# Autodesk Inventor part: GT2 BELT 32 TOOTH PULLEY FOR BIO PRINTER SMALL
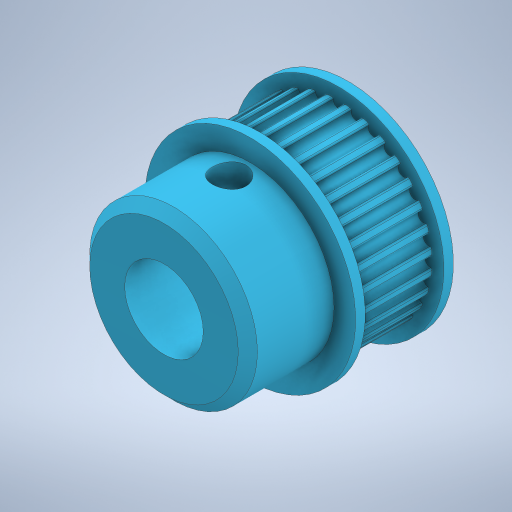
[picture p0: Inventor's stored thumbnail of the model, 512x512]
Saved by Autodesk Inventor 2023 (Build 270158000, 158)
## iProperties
Created: 2025-07
Part Number: GT2 BELT 32 TOOTH PULLEY FOR BIO PRINTER SMALL
Material: Generic
Document SubType Name: Modeling
Designer: erjon
Density: 1 g/cm^3
Appearance: Default
Author: erjon
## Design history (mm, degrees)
feature "Base1"
sketch "Sketch1"
  geometry: 1 further point
sketch "Sketch2"
  geometry: C1 r 10 at (0, 0) reference; C2 r 10 at (0, 0); 1 further point
  constraints: 1 centre point, 1 coincident
extrude "Extrusion1" cut sketch "Sketch2" distance "d0" = 6.2; taper "d1" = 0 deg
sketch "Sketch3" dims "d2" = 19.57
  geometry: L1 (0, 9.785)-(0, 9.035); L2 (0, 9.035)-(0, 9.585); C1 r 4 at (0, 0); A1 r 0.55 centre (0, 9.585) between (-0.517, 9.771) and (0.517, 9.771); A2 r 0.55 centre (-1.87, 9.401) between (-2.414, 9.483) and (-1.399, 9.685); A3 r 0.55 centre (-3.668, 8.855) between (-4.217, 8.829) and (-3.261, 9.226); A4 r 0.55 centre (-5.325, 7.97) between (-5.859, 7.837) and (-4.998, 8.412); A5 r 0.55 centre (-6.778, 6.778) between (-7.275, 6.543) and (-6.543, 7.275); A6 r 0.55 centre (-7.97, 5.325) between (-8.412, 4.998) and (-7.837, 5.859); A7 r 0.55 centre (-8.855, 3.668) between (-9.226, 3.261) and (-8.829, 4.217); A8 r 0.55 centre (-9.401, 1.87) between (-9.685, 1.399) and (-9.483, 2.414); A9 r 0.55 centre (-9.585, 0) between (-9.771, -0.517) and (-9.771, 0.517); A10 r 0.55 centre (-9.401, -1.87) between (-9.483, -2.414) and (-9.685, -1.399); A11 r 0.55 centre (-8.855, -3.668) between (-8.829, -4.217) and (-9.226, -3.261); A12 r 0.55 centre (-7.97, -5.325) between (-7.837, -5.859) and (-8.412, -4.998); A13 r 0.55 centre (-6.778, -6.778) between (-6.543, -7.275) and (-7.275, -6.543); A14 r 0.55 centre (-5.325, -7.97) between (-4.998, -8.412) and (-5.859, -7.837); A15 r 0.55 centre (-3.668, -8.855) between (-3.261, -9.226) and (-4.217, -8.829); A16 r 0.55 centre (-1.87, -9.401) between (-1.399, -9.685) and (-2.414, -9.483); A17 r 0.55 centre (0, -9.585) between (0.517, -9.771) and (-0.517, -9.771); A18 r 0.55 centre (1.87, -9.401) between (2.414, -9.483) and (1.399, -9.685); A19 r 0.55 centre (3.668, -8.855) between (4.217, -8.829) and (3.261, -9.226); A20 r 0.55 centre (5.325, -7.97) between (5.859, -7.837) and (4.998, -8.412); A21 r 0.55 centre (6.778, -6.778) between (7.275, -6.543) and (6.543, -7.275); A22 r 0.55 centre (7.97, -5.325) between (8.412, -4.998) and (7.837, -5.859); A23 r 0.55 centre (8.855, -3.668) between (9.226, -3.261) and (8.829, -4.217); A24 r 0.55 centre (9.401, -1.87) between (9.685, -1.399) and (9.483, -2.414); A25 r 0.55 centre (9.585, 0) between (9.771, 0.517) and (9.771, -0.517); A26 r 0.55 centre (9.401, 1.87) between (9.483, 2.414) and (9.685, 1.399); A27 r 0.55 centre (8.855, 3.668) between (8.829, 4.217) and (9.226, 3.261); A28 r 0.55 centre (7.97, 5.325) between (7.837, 5.859) and (8.412, 4.998); A29 r 0.55 centre (6.778, 6.778) between (6.543, 7.275) and (7.275, 6.543); A30 r 0.55 centre (5.325, 7.97) between (4.998, 8.412) and (5.859, 7.837); A31 r 0.55 centre (3.668, 8.855) between (3.261, 9.226) and (4.217, 8.829); A32 r 0.55 centre (1.87, 9.401) between (1.399, 9.685) and (2.414, 9.483); A33 r 0.15 centre (-0.7, 9.61) between (-0.55, 9.604) and (-0.71, 9.759); A34 r 0.15 centre (-1.189, 9.561) between (-1.207, 9.71) and (-1.335, 9.527); A35 r 0.15 centre (-2.561, 9.288) between (-2.413, 9.313) and (-2.601, 9.433); A36 r 0.15 centre (-3.031, 9.146) between (-3.078, 9.288) and (-3.168, 9.084); A37 r 0.15 centre (-4.324, 8.61) between (-4.183, 8.663) and (-4.391, 8.744); A38 r 0.15 centre (-4.757, 8.379) between (-4.831, 8.509) and (-4.879, 8.291); A39 r 0.15 centre (-5.92, 7.601) between (-5.793, 7.68) and (-6.013, 7.72); A40 r 0.15 centre (-6.3, 7.29) between (-6.398, 7.403) and (-6.403, 7.18); A41 r 0.15 centre (-7.29, 6.3) between (-7.18, 6.403) and (-7.403, 6.398); A42 r 0.15 centre (-7.601, 5.92) between (-7.72, 6.013) and (-7.68, 5.793); A43 r 0.15 centre (-8.379, 4.757) between (-8.291, 4.879) and (-8.509, 4.831); A44 r 0.15 centre (-8.61, 4.324) between (-8.744, 4.391) and (-8.663, 4.183); A45 r 0.15 centre (-9.146, 3.031) between (-9.084, 3.168) and (-9.288, 3.078); A46 r 0.15 centre (-9.288, 2.561) between (-9.433, 2.601) and (-9.313, 2.413); A47 r 0.15 centre (-9.561, 1.189) between (-9.527, 1.335) and (-9.71, 1.207); A48 r 0.15 centre (-9.61, 0.7) between (-9.759, 0.71) and (-9.604, 0.55); A49 r 0.15 centre (-9.61, -0.7) between (-9.604, -0.55) and (-9.759, -0.71); A50 r 0.15 centre (-9.561, -1.189) between (-9.71, -1.207) and (-9.527, -1.335); A51 r 0.15 centre (-9.288, -2.561) between (-9.313, -2.413) and (-9.433, -2.601); A52 r 0.15 centre (-9.146, -3.031) between (-9.288, -3.078) and (-9.084, -3.168); A53 r 0.15 centre (-8.61, -4.324) between (-8.663, -4.183) and (-8.744, -4.391); A54 r 0.15 centre (-8.379, -4.757) between (-8.509, -4.831) and (-8.291, -4.879); A55 r 0.15 centre (-7.601, -5.92) between (-7.68, -5.793) and (-7.72, -6.013); A56 r 0.15 centre (-7.29, -6.3) between (-7.403, -6.398) and (-7.18, -6.403); A57 r 0.15 centre (-6.3, -7.29) between (-6.403, -7.18) and (-6.398, -7.403); A58 r 0.15 centre (-5.92, -7.601) between (-6.013, -7.72) and (-5.793, -7.68); A59 r 0.15 centre (-4.757, -8.379) between (-4.879, -8.291) and (-4.831, -8.509); A60 r 0.15 centre (-4.324, -8.61) between (-4.391, -8.744) and (-4.183, -8.663); A61 r 0.15 centre (-3.031, -9.146) between (-3.168, -9.084) and (-3.078, -9.288); A62 r 0.15 centre (-2.561, -9.288) between (-2.601, -9.433) and (-2.413, -9.313); A63 r 0.15 centre (-1.189, -9.561) between (-1.335, -9.527) and (-1.207, -9.71); A64 r 0.15 centre (-0.7, -9.61) between (-0.71, -9.759) and (-0.55, -9.604)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; 157 further points
  constraints: 226 point on circle, 97 centre point, 4 end point, 3 coincident, 2 tangent, 1 point on line, 1 vertical, 427 other
  dimensions: "d3" = 0.75 distance of L1.start L1.end; "d4" = 0.55 distance of L1.end L2.end; "d7" = 360 deg dimension on point (0, 0) A1.centre (derived); "d9" = 0.3 diameter of A33; "d10" = 0.3 diameter of A34; "d13" = 360 deg dimension on point (0, 0) A33.centre (derived)
extrude "Extrusion2" join sketch "Sketch3" distance "d15" = 6.3; taper "d16" = 0 deg
sketch "Sketch4"
  geometry: C1 r 4 at (0, 0); 1 further point
  constraints: 1 centre point, 1 coincident
extrude "Extrusion3" join sketch "Sketch4" distance "d17" = 17.2; taper "d18" = 0 deg
sketch "Sketch5"
  geometry: L1 (1.533, 2.1)-(-1.533, 2.1); A1 r 2.6 centre (0, 0) between (-1.533, 2.1) and (1.533, 2.1); 1 further point
  constraints: 2 end point, 2 point on circle, 1 centre point, 1 coincident
extrude "Extrusion4" cut sketch "Sketch5" distance "d22" = 17.2; taper "d23" = 0 deg
sketch "Sketch6"
  geometry: C1 r 2.6 at (0, 0); 1 further point
  constraints: 1 centre point, 1 coincident
extrude "Extrusion5" cut sketch "Sketch6" distance "d24" = 4; taper "d25" = 0 deg
sketch "Sketch7"
  geometry: L1 (-2.6, 9)-(2.6, 9) reference; L2 (8.75, 0)-(-8.75, 0) reference; L3 (0, 0)-(0, 2.2); C1 r 1.75 at (0, 2.2)
  constraints: 2 end point, 1 centre point, 1 coincident
  dimensions: "d26" = 2.2 distance of L3.start L3.end; "d27" = 3.5 diameter of C1
extrude "Extrusion6" cut sketch "Sketch7" distance "d28" = 10; taper "d29" = 0 deg
sketch "Sketch8"
  geometry: C1 r 4 at (0, 0); 1 further point
  constraints: 1 centre point, 1 coincident
  dimensions: "d30" = 8 diameter of C1
extrude "Extrusion7" cut sketch "Sketch8" distance "d31" = 50; taper "d32" = 0 deg
sketch "Sketch9"
  geometry: C1 r 12.5 at (0, 0); 1 further point
  constraints: 1 centre point, 1 coincident
extrude "Extrusion8" cut sketch "Sketch9" distance "d33" = 10; taper "d34" = 0 deg
sketch "Sketch10"
  geometry: C1 r 4 at (0, 0) reference; A1 r 9.785 centre (0, 0) between (0.71, -9.759) and (1.207, -9.71) reference; A2 r 0.15 centre (1.189, -9.561) between (1.207, -9.71) and (1.335, -9.527) reference; A3 r 0.55 centre (1.87, -9.401) between (2.413, -9.313) and (1.335, -9.527) reference; A4 r 0.15 centre (2.561, -9.288) between (2.413, -9.313) and (2.601, -9.433) reference; A5 r 9.785 centre (0, 0) between (2.601, -9.433) and (3.078, -9.288) reference; A6 r 0.15 centre (3.031, -9.146) between (3.078, -9.288) and (3.168, -9.084) reference; A7 r 0.55 centre (3.668, -8.855) between (4.183, -8.663) and (3.168, -9.084) reference; A8 r 0.15 centre (4.324, -8.61) between (4.183, -8.663) and (4.391, -8.744) reference; A9 r 9.785 centre (0, 0) between (4.391, -8.744) and (4.831, -8.509) reference; A10 r 0.15 centre (4.757, -8.379) between (4.831, -8.509) and (4.879, -8.291) reference; A11 r 0.55 centre (5.325, -7.97) between (5.793, -7.68) and (4.879, -8.291) reference; A12 r 0.15 centre (5.92, -7.601) between (5.793, -7.68) and (6.013, -7.72) reference; A13 r 9.785 centre (0, 0) between (6.013, -7.72) and (6.398, -7.403) reference; A14 r 0.15 centre (6.3, -7.29) between (6.398, -7.403) and (6.403, -7.18) reference; A15 r 0.55 centre (6.778, -6.778) between (7.18, -6.403) and (6.403, -7.18) reference; A16 r 0.15 centre (7.29, -6.3) between (7.18, -6.403) and (7.403, -6.398) reference; A17 r 9.785 centre (0, 0) between (7.403, -6.398) and (7.72, -6.013) reference; A18 r 0.15 centre (7.601, -5.92) between (7.72, -6.013) and (7.68, -5.793) reference; A19 r 0.55 centre (7.97, -5.325) between (8.291, -4.879) and (7.68, -5.793) reference; A20 r 0.15 centre (8.379, -4.757) between (8.291, -4.879) and (8.509, -4.831) reference; A21 r 9.785 centre (0, 0) between (8.509, -4.831) and (8.744, -4.391) reference; A22 r 0.15 centre (8.61, -4.324) between (8.744, -4.391) and (8.663, -4.183) reference; A23 r 0.55 centre (8.855, -3.668) between (9.084, -3.168) and (8.663, -4.183) reference; A24 r 0.15 centre (9.146, -3.031) between (9.084, -3.168) and (9.288, -3.078) reference; A25 r 9.785 centre (0, 0) between (9.288, -3.078) and (9.433, -2.601) reference; A26 r 0.15 centre (9.288, -2.561) between (9.433, -2.601) and (9.313, -2.413) reference; A27 r 0.55 centre (9.401, -1.87) between (9.527, -1.335) and (9.313, -2.413) reference; A28 r 0.15 centre (9.561, -1.189) between (9.527, -1.335) and (9.71, -1.207) reference; A29 r 9.785 centre (0, 0) between (9.71, -1.207) and (9.759, -0.71) reference; A30 r 0.15 centre (9.61, -0.7) between (9.759, -0.71) and (9.604, -0.55) reference; A31 r 0.55 centre (9.585, 0) between (9.604, 0.55) and (9.604, -0.55) reference; A32 r 0.15 centre (9.61, 0.7) between (9.604, 0.55) and (9.759, 0.71) reference; A33 r 9.785 centre (0, 0) between (9.759, 0.71) and (9.71, 1.207) reference; A34 r 0.15 centre (9.561, 1.189) between (9.71, 1.207) and (9.527, 1.335) reference; A35 r 0.55 centre (9.401, 1.87) between (9.313, 2.413) and (9.527, 1.335) reference; A36 r 0.15 centre (9.288, 2.561) between (9.313, 2.413) and (9.433, 2.601) reference; A37 r 9.785 centre (0, 0) between (9.433, 2.601) and (9.288, 3.078) reference; A38 r 0.15 centre (9.146, 3.031) between (9.288, 3.078) and (9.084, 3.168) reference; A39 r 0.55 centre (8.855, 3.668) between (8.663, 4.183) and (9.084, 3.168) reference; A40 r 0.15 centre (8.61, 4.324) between (8.663, 4.183) and (8.744, 4.391) reference; A41 r 9.785 centre (0, 0) between (8.744, 4.391) and (8.509, 4.831) reference; A42 r 0.15 centre (8.379, 4.757) between (8.509, 4.831) and (8.291, 4.879) reference; A43 r 0.55 centre (7.97, 5.325) between (7.68, 5.793) and (8.291, 4.879) reference; A44 r 0.15 centre (7.601, 5.92) between (7.68, 5.793) and (7.72, 6.013) reference; A45 r 9.785 centre (0, 0) between (7.72, 6.013) and (7.403, 6.398) reference; A46 r 0.15 centre (7.29, 6.3) between (7.403, 6.398) and (7.18, 6.403) reference; A47 r 0.55 centre (6.778, 6.778) between (6.403, 7.18) and (7.18, 6.403) reference; A48 r 0.15 centre (6.3, 7.29) between (6.403, 7.18) and (6.398, 7.403) reference; A49 r 9.785 centre (0, 0) between (6.398, 7.403) and (6.013, 7.72) reference; A50 r 0.15 centre (5.92, 7.601) between (6.013, 7.72) and (5.793, 7.68) reference; A51 r 0.55 centre (5.325, 7.97) between (4.879, 8.291) and (5.793, 7.68) reference; A52 r 0.15 centre (4.757, 8.379) between (4.879, 8.291) and (4.831, 8.509) reference; A53 r 9.785 centre (0, 0) between (4.831, 8.509) and (4.391, 8.744) reference; A54 r 0.15 centre (4.324, 8.61) between (4.391, 8.744) and (4.183, 8.663) reference; A55 r 0.55 centre (3.668, 8.855) between (3.168, 9.084) and (4.183, 8.663) reference; A56 r 0.15 centre (3.031, 9.146) between (3.168, 9.084) and (3.078, 9.288) reference; A57 r 9.785 centre (0, 0) between (3.078, 9.288) and (2.601, 9.433) reference; A58 r 0.15 centre (2.561, 9.288) between (2.601, 9.433) and (2.413, 9.313) reference; A59 r 0.55 centre (1.87, 9.401) between (1.335, 9.527) and (2.413, 9.313) reference; A60 r 0.15 centre (1.189, 9.561) between (1.335, 9.527) and (1.207, 9.71) reference; A61 r 9.785 centre (0, 0) between (1.207, 9.71) and (0.71, 9.759) reference; A62 r 0.15 centre (0.7, 9.61) between (0.71, 9.759) and (0.55, 9.604) reference; A63 r 0.55 centre (0, 9.585) between (-0.55, 9.604) and (0.55, 9.604) reference; A64 r 0.15 centre (-0.7, 9.61) between (-0.55, 9.604) and (-0.71, 9.759) reference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; 1 further point
extrude "Extrusion9" join sketch "Sketch10" distance "d35" = 2; taper "d36" = 0 deg
sketch "Sketch11"
  geometry: C1 r 12.5 at (0, 0); 1 further point
  constraints: 1 centre point, 1 coincident
extrude "Extrusion10" join sketch "Sketch11" distance "d37" = 1; taper "d38" = 0 deg
sketch "Sketch13"
  geometry: C1 r 12.5 at (0, 0) reference; C2 r 11 at (0, 0); 1 further point
  constraints: 1 centre point, 1 coincident
  dimensions: "d39" = 22 diameter of C2
extrude "Extrusion11" cut sketch "Sketch13" stored distance "d40" = 100; taper "d41" = 0 deg
sketch "Sketch14"
  geometry: C1 r 4.1 at (0, 0); 1 further point
  constraints: 1 centre point, 1 coincident
  dimensions: "d42" = 8.2 diameter of C1
extrude "Extrusion12" cut sketch "Sketch14" distance "d43" = 50; taper "d44" = 0 deg
body "Solid1"
node "Projected Loop1"
